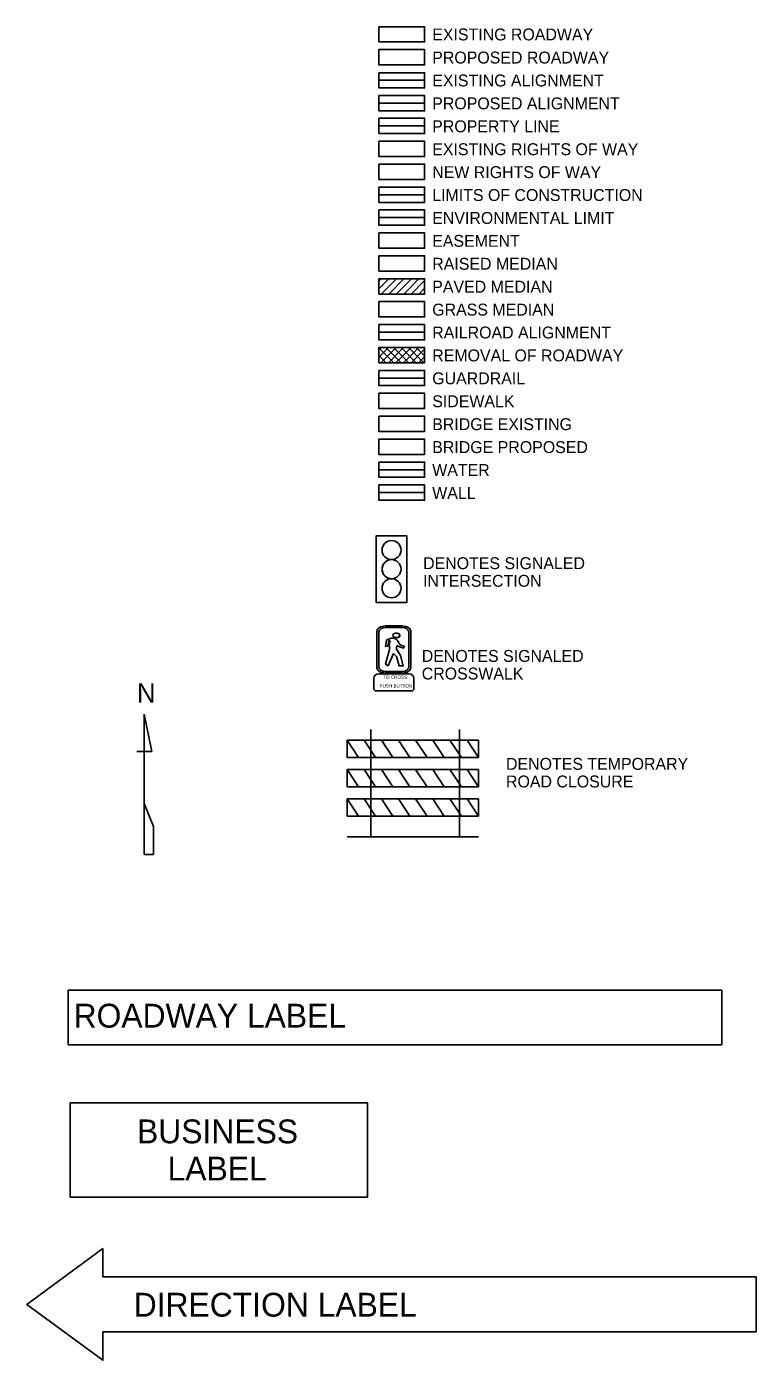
# Model space of a CAD drawing. Extents: x -1064 to 1826, y -89 to 1039.
# Drawn here: x -1064 to -602, y -89 to 755 of the extents above; entities that cross this region are included whole.
import ezdxf

# ---------------------------------------------------------------- set-up
doc = ezdxf.new("R2010")
doc.units = 0
for name, color, linetype in [('PIM_ALIGN_EX', 7, 'Continuous'), ('PIM_ALIGN_PD', 7, 'Continuous'), ('PIM_BORDER_SHEET', 7, 'Continuous'), ('PIM_BRIDGE_EX', 7, 'Continuous'), ('PIM_BRIDGE_PD', 7, 'Continuous'), ('PIM_CELLS', 7, 'Continuous'), ('PIM_CONST_LIM', 7, 'Continuous'), ('PIM_EASEMENT', 7, 'Continuous'), ('PIM_GUARDRAIL', 7, 'Continuous'), ('PIM_MED_CONC', 7, 'Continuous'), ('PIM_MED_GRASS', 7, 'Continuous'), ('PIM_PAVE_ASPH_EX', 7, 'Continuous'), ('PIM_PAVE_ASPH_PD', 7, 'Continuous'), ('PIM_PAVE_MARK', 7, 'Continuous'), ('PIM_PAVE_REMOVAL', 7, 'Continuous'), ('PIM_PROPERTY_LINE', 7, 'Continuous'), ('PIM_RAILROAD', 7, 'Continuous'), ('PIM_ROW_EX', 7, 'Continuous'), ('PIM_ROW_PD', 7, 'Continuous'), ('PIM_SW_CONC', 7, 'Continuous'), ('PIM_WALLS', 7, 'Continuous'), ('PIM_WATER', 7, 'Continuous'), ('PIM_WETLAND', 7, 'Continuous')]:
    doc.layers.add(name, color=color, linetype=linetype)

msp = doc.modelspace()

# ---------------------------------------------------------------- linework, layer by layer
at = {"layer": 'PIM_ALIGN_EX'}
msp.add_line((-841.13, 720.88), (-812.18, 720.88), dxfattribs=at)
at = {"layer": 'PIM_ALIGN_PD'}
msp.add_line((-841.13, 706.37), (-812.18, 706.37), dxfattribs=at)
at = {"layer": 'PIM_BORDER_SHEET'}
msp.add_line((-778.08, 242.07), (-861.27, 242.07), dxfattribs=at)
for points in [[(-846.17, 310.03), (-846.17, 242.07)], [(-790.11, 242.07), (-790.11, 310.03)]]:
    msp.add_lwpolyline(points, dxfattribs=at)
for points in [[(-778.08, 303.16), (-861.27, 303.16), (-861.27, 292.29), (-778.08, 292.29)], [(-861.27, 303.16), (-854.04, 292.29), (-843.19, 292.29), (-850.42, 303.16)], [(-839.57, 303.16), (-832.34, 292.29), (-821.49, 292.29), (-828.72, 303.16)], [(-817.87, 303.16), (-810.64, 292.29), (-799.78, 292.29), (-807.02, 303.16)], [(-796.17, 303.16), (-788.93, 292.29), (-778.08, 292.29), (-785.32, 303.16)], [(-778.08, 284.6), (-861.27, 284.6), (-861.27, 273.73), (-778.08, 273.73)], [(-861.27, 284.6), (-854.04, 273.73), (-843.19, 273.73), (-850.42, 284.6)], [(-839.57, 284.6), (-832.34, 273.73), (-821.49, 273.73), (-828.72, 284.6)], [(-817.87, 284.6), (-810.64, 273.73), (-799.78, 273.73), (-807.02, 284.6)], [(-796.17, 284.6), (-788.93, 273.73), (-778.08, 273.73), (-785.32, 284.6)], [(-778.08, 266.04), (-861.27, 266.04), (-861.27, 255.17), (-778.08, 255.17)], [(-861.27, 266.04), (-854.04, 255.17), (-843.19, 255.17), (-850.42, 266.04)], [(-839.57, 266.04), (-832.34, 255.17), (-821.49, 255.17), (-828.72, 266.04)], [(-817.87, 266.04), (-810.64, 255.17), (-799.78, 255.17), (-807.02, 266.04)], [(-796.17, 266.04), (-788.93, 255.17), (-778.08, 255.17), (-785.32, 266.04)], [(-1015.86, -18.43), (-1064.09, -53.86), (-1015.86, -89.28), (-1015.86, -71.19), (-602.2, -71.19), (-602.2, -36.52), (-1015.86, -36.52)]]:
    msp.add_lwpolyline(points, close=True, dxfattribs=at)
at = {"layer": 'PIM_BRIDGE_EX'}
msp.add_lwpolyline([(-841.13, 508.29), (-812.18, 508.29), (-812.18, 498.62), (-841.13, 498.62)], close=True, dxfattribs=at)
at = {"layer": 'PIM_BRIDGE_PD'}
msp.add_lwpolyline([(-841.13, 493.79), (-812.18, 493.79), (-812.18, 484.12), (-841.13, 484.12)], close=True, dxfattribs=at)
at = {"layer": 'PIM_CELLS'}
for p, q in [((-842.51, 371.74), (-842.51, 349.52)), ((-841.1, 349.52), (-841.1, 371.74)), ((-841.1, 371.74), (-841.1, 349.52)), ((-831.66, 375.52), (-836.85, 375.52)), ((-836.85, 374.57), (-831.66, 374.57)), ((-831.66, 374.57), (-836.85, 374.57)), ((-826.46, 375.52), (-831.66, 375.52)), ((-831.66, 374.57), (-826.46, 374.57)), ((-826.46, 374.57), (-831.66, 374.57)), ((-822.22, 371.74), (-822.22, 349.52)), ((-822.22, 349.52), (-822.22, 371.74)), ((-820.8, 349.52), (-820.8, 371.74)), ((-835.52, 362.66), (-834.87, 366.1)), ((-834.87, 366.1), (-835.52, 362.66)), ((-833.27, 367.74), (-833.28, 367.74)), ((-833.28, 367.74), (-833.28, 367.74)), ((-829.67, 363.24), (-828.17, 362.26)), ((-828.17, 362.26), (-829.67, 363.24)), ((-829.55, 366.61), (-827.66, 363.56)), ((-825, 362.57), (-827.66, 363.56)), ((-827.66, 363.56), (-825, 362.57)), ((-834.18, 361.49), (-837.02, 351.26)), ((-837.02, 351.26), (-834.18, 361.49)), ((-836.84, 362.62), (-835.52, 362.66)), ((-835.52, 362.66), (-836.84, 362.62)), ((-835.34, 350.23), (-831.92, 358.06)), ((-831.92, 358.06), (-835.34, 350.23)), ((-837.02, 351.26), (-835.34, 350.23)), ((-835.34, 350.23), (-837.02, 351.26)), ((-831.66, 346.68), (-836.85, 346.68)), ((-836.85, 346.68), (-831.66, 346.68)), ((-826.46, 346.68), (-831.66, 346.68)), ((-831.66, 346.68), (-826.46, 346.68)), ((-844.34, 342.34), (-844.34, 335.78)), ((-844.34, 342.34), (-844.34, 335.78)), ((-831.66, 345.22), (-841.1, 345.22)), ((-831.66, 345.22), (-841.1, 345.22)), ((-836.85, 345.74), (-831.66, 345.74)), ((-831.66, 345.74), (-826.46, 345.74)), ((-822.21, 345.22), (-831.66, 345.22)), ((-822.21, 345.22), (-831.66, 345.22)), ((-818.97, 335.78), (-818.97, 342.34)), ((-818.97, 335.78), (-818.97, 342.34)), ((-842.87, 334.47), (-831.66, 334.47)), ((-842.87, 334.47), (-831.66, 334.47)), ((-831.66, 334.47), (-820.44, 334.47)), ((-831.66, 334.47), (-820.44, 334.47)), ((-984.93, 295.99), (-989.65, 319.67)), ((-989.65, 319.67), (-989.65, 319.67)), ((-989.65, 319.67), (-989.65, 295.99)), ((-994.38, 295.99), (-989.65, 295.99)), ((-989.65, 263.12), (-989.65, 295.99)), ((-989.65, 295.99), (-984.93, 295.99)), ((-984.93, 295.99), (-984.93, 296.27)), ((-983.75, 248.62), (-989.65, 263.12)), ((-989.65, 263.12), (-989.65, 230.85)), ((-983.75, 230.85), (-983.75, 248.78)), ((-983.75, 248.78), (-983.75, 248.62)), ((-989.65, 230.85), (-983.75, 230.85))]:
    msp.add_line(p, q, dxfattribs=at)
for points in [[(-823.47, 432.62), (-842.76, 432.62), (-842.76, 390.33), (-823.47, 390.33), (-823.47, 432.62)], [(-833.28, 367.74), (-836.39, 366.45), (-836.84, 362.62)], [(-836.84, 362.62), (-836.39, 366.45), (-833.27, 367.74)], [(-834.87, 366.1), (-834.06, 366.1), (-834.59, 364.18)], [(-834.59, 364.18), (-834.06, 366.1), (-834.87, 366.1)], [(-827.66, 363.56), (-829.55, 366.61), (-829.55, 366.61)], [(-831.92, 358.06), (-830, 356.14), (-828.3, 350.23), (-825.67, 350.23), (-827.54, 356.74), (-830.18, 361.21)], [(-830.18, 361.21), (-827.54, 356.74), (-825.67, 350.23), (-828.3, 350.23), (-830, 356.14), (-831.92, 358.06)], [(-828.17, 362.26), (-825.61, 361.57), (-825, 362.57)], [(-825, 362.57), (-825.61, 361.57), (-828.17, 362.26)]]:
    msp.add_lwpolyline(points, dxfattribs=at)
for points in [[(-842.76, 432.62), (-823.47, 432.62), (-823.47, 390.33), (-842.76, 390.33)], [(-1037.8, 145.08), (-624.14, 145.08), (-624.14, 110.4), (-1037.8, 110.4)], [(-1036.5, 73.64), (-848.44, 73.64), (-848.44, 14.07), (-1036.5, 14.07)]]:
    msp.add_lwpolyline(points, close=True, dxfattribs=at)
for centre in [(-833.12, 423.56), (-833.12, 423.56), (-833.12, 423.56), (-833.12, 411.48), (-833.12, 411.48), (-833.12, 399.39), (-833.12, 399.39), (-833.12, 399.39)]:
    msp.add_ellipse(centre, major_axis=(0, 6.04), ratio=0.997778, dxfattribs=at)
for centre, major_axis, ratio, start_param, end_param in [((-833.12, 411.48), (0, 6.04), 0.997778, 0, 3.141593), ((-833.12, 411.48), (0, 6.04), 0.997778, 3.141593, 6.283185), ((-836.85, 371.74), (-5.66, 0), 0.668151, 4.712389, 6.283185), ((-836.85, 371.74), (-4.25, 0), 0.668151, 4.712389, 6.283185), ((-836.85, 371.74), (-4.25, 0), 0.668151, 4.712389, 6.283185), ((-826.46, 371.74), (5.66, 0), 0.668151, 0, 1.570796), ((-826.46, 371.74), (4.25, 0), 0.668151, 0, 1.570796), ((-826.46, 371.74), (4.25, 0), 0.668151, 0, 1.570796), ((-819.13, 363.86), (-15.46, 0), 0.668151, 6.252761, 6.515412), ((-819.13, 363.86), (-15.46, 0), 0.668151, 6.252761, 6.515412), ((-832.31, 365.85), (-2.99, 0), 0.668151, 3.53524, 5.041115), ((-832.31, 365.85), (-2.99, 0), 0.668151, 3.53524, 5.041115), ((-830.1, 369.58), (2.2, 0), 0.668151, 1.84251, 3.141593), ((-830.1, 369.58), (2.2, 0), 0.668151, 1.84251, 3.141593), ((-830.1, 369.58), (2.2, 0), 0.668151, 3.141593, 4.440675), ((-830.1, 369.58), (2.2, 0), 0.668151, 3.141593, 4.440675), ((-830.1, 369.58), (2.2, 0), 0.668151, 1.299083, 1.84251), ((-830.1, 369.58), (2.2, 0), 0.668151, 1.299083, 1.84251), ((-830.1, 369.58), (2.2, 0), 0.668151, 4.440675, 7.582268), ((-830.1, 369.58), (2.2, 0), 0.668151, 4.440675, 6.283185), ((-790.87, 357.79), (-39.65, 0), 0.668151, 6.075978, 6.153718), ((-790.87, 357.79), (-39.65, 0), 0.668151, 6.075978, 6.153718), ((-830.1, 369.58), (2.2, 0), 0.668151, 0, 1.299083), ((-836.85, 349.52), (-5.66, 0), 0.668151, 0, 1.570796), ((-836.85, 349.52), (-4.25, 0), 0.668151, 0, 1.570796), ((-836.85, 349.52), (-4.25, 0), 0.668151, 0, 1.570796), ((-826.46, 349.52), (5.66, 0), 0.668151, 4.712389, 6.283185), ((-826.46, 349.52), (4.25, 0), 0.668151, 4.712389, 6.283185), ((-826.46, 349.52), (4.25, 0), 0.668151, 4.712389, 6.283185), ((-841.1, 342.34), (-3.24, 0), 0.890869, 4.712389, 6.283185), ((-841.1, 342.34), (-3.24, 0), 0.890869, 4.712389, 6.283185), ((-822.21, 342.34), (3.24, 0), 0.890869, 0, 1.570796), ((-822.21, 342.34), (3.24, 0), 0.890869, 0, 1.570796), ((-842.87, 335.78), (1.47, 0), 0.890869, 3.141593, 4.712389), ((-842.87, 335.78), (1.47, 0), 0.890869, 3.141593, 4.712389), ((-820.44, 335.78), (1.47, 0), 0.890869, 4.712389, 6.283185), ((-820.44, 335.78), (1.47, 0), 0.890869, 4.712389, 6.283185)]:
    msp.add_ellipse(centre, major_axis=major_axis, ratio=ratio, start_param=start_param, end_param=end_param, dxfattribs=at)
at = {"layer": 'PIM_CONST_LIM'}
msp.add_line((-841.13, 648.49), (-812.18, 648.49), dxfattribs=at)
at = {"layer": 'PIM_EASEMENT'}
msp.add_lwpolyline([(-841.13, 624.32), (-812.18, 624.32), (-812.18, 614.65), (-841.13, 614.65)], close=True, dxfattribs=at)
at = {"layer": 'PIM_GUARDRAIL'}
msp.add_line((-841.13, 532.46), (-812.18, 532.46), dxfattribs=at)
at = {"layer": 'PIM_MED_CONC'}
msp.add_lwpolyline([(-812.18, 600.14), (-812.18, 609.81), (-841.13, 609.81), (-841.13, 600.14), (-812.18, 600.14)], dxfattribs=at)
msp.add_lwpolyline([(-841.13, 609.81), (-812.18, 609.81), (-812.18, 600.14), (-841.13, 600.14)], close=True, dxfattribs=at)
at = {"layer": 'PIM_MED_GRASS'}
for points in [[(-841.13, 696.83), (-812.18, 696.83), (-812.18, 687.16), (-841.13, 687.16)], [(-841.13, 653.32), (-812.18, 653.32), (-812.18, 643.65), (-841.13, 643.65)], [(-841.13, 638.82), (-812.18, 638.82), (-812.18, 629.15), (-841.13, 629.15)], [(-841.13, 580.81), (-812.18, 580.81), (-812.18, 571.14), (-841.13, 571.14)], [(-841.13, 479.29), (-812.18, 479.29), (-812.18, 469.62), (-841.13, 469.62)], [(-841.13, 464.78), (-812.18, 464.78), (-812.18, 455.11), (-841.13, 455.11)]]:
    msp.add_lwpolyline(points, close=True, dxfattribs=at)
at = {"layer": 'PIM_PAVE_ASPH_EX'}
for points in [[(-841.13, 754.84), (-812.18, 754.84), (-812.18, 745.17), (-841.13, 745.17)], [(-841.13, 725.71), (-812.18, 725.71), (-812.18, 716.04), (-841.13, 716.04)], [(-841.13, 711.21), (-812.18, 711.21), (-812.18, 701.54), (-841.13, 701.54)], [(-841.13, 566.3), (-812.18, 566.3), (-812.18, 556.63), (-841.13, 556.63)], [(-841.13, 551.8), (-812.18, 551.8), (-812.18, 542.13), (-841.13, 542.13)]]:
    msp.add_lwpolyline(points, close=True, dxfattribs=at)
at = {"layer": 'PIM_PAVE_ASPH_PD'}
for points in [[(-841.13, 740.34), (-812.18, 740.34), (-812.18, 730.67), (-841.13, 730.67)], [(-841.13, 537.3), (-812.18, 537.3), (-812.18, 527.63), (-841.13, 527.63)]]:
    msp.add_lwpolyline(points, close=True, dxfattribs=at)
at = {"layer": 'PIM_PAVE_MARK'}
for p, q in [((-841.13, 589.01), (-834.84, 595.31)), ((-841.13, 593.79), (-839.61, 595.31)), ((-839.71, 585.64), (-830.06, 595.31)), ((-834.93, 585.64), (-825.29, 595.31)), ((-830.16, 585.64), (-820.51, 595.31)), ((-825.38, 585.64), (-815.74, 595.31)), ((-820.61, 585.64), (-812.18, 594.08)), ((-813.06, 595.31), (-812.18, 594.43)), ((-815.83, 585.64), (-812.18, 589.3))]:
    msp.add_line(p, q, dxfattribs=at)
msp.add_lwpolyline([(-841.13, 595.31), (-812.18, 595.31), (-812.18, 585.64), (-841.13, 585.64)], close=True, dxfattribs=at)
msp.add_lwpolyline([(-841.13, 585.64), (-812.18, 585.64), (-812.18, 595.31), (-841.13, 595.31), (-841.13, 585.64)], dxfattribs=at)
at = {"layer": 'PIM_PAVE_REMOVAL'}
for p, q in [((-841.13, 545.66), (-835, 551.8)), ((-841.13, 550.44), (-839.77, 551.8)), ((-841.13, 551.5), (-831.77, 542.13)), ((-839.87, 542.13), (-830.22, 551.8)), ((-836.65, 551.8), (-827, 542.13)), ((-835.09, 542.13), (-825.45, 551.8)), ((-831.87, 551.8), (-822.22, 542.13)), ((-830.32, 542.13), (-820.67, 551.8)), ((-827.1, 551.8), (-817.45, 542.13)), ((-825.54, 542.13), (-815.9, 551.8)), ((-822.32, 551.8), (-812.67, 542.13)), ((-820.77, 542.13), (-812.18, 550.74)), ((-817.55, 551.8), (-812.18, 546.43)), ((-812.77, 551.8), (-812.18, 551.21)), ((-841.13, 546.72), (-836.55, 542.13)), ((-815.99, 542.13), (-812.18, 545.95))]:
    msp.add_line(p, q, dxfattribs=at)
msp.add_lwpolyline([(-841.13, 542.13), (-812.18, 542.13), (-812.18, 551.8), (-841.13, 551.8), (-841.13, 542.13)], dxfattribs=at)
at = {"layer": 'PIM_PROPERTY_LINE'}
msp.add_line((-841.13, 692), (-812.18, 692), dxfattribs=at)
at = {"layer": 'PIM_RAILROAD'}
msp.add_line((-841.13, 561.47), (-812.18, 561.47), dxfattribs=at)
at = {"layer": 'PIM_ROW_EX'}
msp.add_lwpolyline([(-841.13, 682.33), (-812.18, 682.33), (-812.18, 672.66), (-841.13, 672.66)], close=True, dxfattribs=at)
msp.add_lwpolyline([(-841.13, 682.33), (-812.18, 682.33), (-812.18, 672.66), (-841.13, 672.66)], close=True, dxfattribs=at)
at = {"layer": 'PIM_ROW_PD'}
for p, q in [((-841.13, 667.82), (-812.18, 667.82)), ((-841.13, 658.16), (-841.13, 667.82)), ((-812.18, 667.82), (-812.18, 658.16)), ((-812.18, 658.16), (-841.13, 658.16))]:
    msp.add_line(p, q, dxfattribs=at)
msp.add_lwpolyline([(-841.13, 667.82), (-812.18, 667.82), (-812.18, 658.16), (-841.13, 658.16)], close=True, dxfattribs=at)
at = {"layer": 'PIM_SW_CONC'}
msp.add_lwpolyline([(-841.13, 522.79), (-812.18, 522.79), (-812.18, 513.13), (-841.13, 513.13)], close=True, dxfattribs=at)
at = {"layer": 'PIM_WALLS'}
msp.add_line((-841.13, 459.95), (-812.18, 459.95), dxfattribs=at)
at = {"layer": 'PIM_WATER'}
msp.add_line((-841.13, 474.45), (-812.18, 474.45), dxfattribs=at)
at = {"layer": 'PIM_WETLAND'}
msp.add_line((-841.13, 633.98), (-812.18, 633.98), dxfattribs=at)

# ---------------------------------------------------------------- texts
at = {"layer": 'PIM_BORDER_SHEET'}
for s, height, p in [('EXISTING ROADWAY', 7.5353, (-807.36, 746.15)), ('PROPOSED ROADWAY', 7.5353, (-807.36, 731.52)), ('EXISTING ALIGNMENT', 7.5353, (-807.36, 717.02)), ('PROPOSED ALIGNMENT', 7.5353, (-807.36, 702.52)), ('PROPERTY LINE', 7.5353, (-807.36, 688.02)), ('EXISTING RIGHTS OF WAY', 7.5353, (-807.36, 673.51)), ('NEW RIGHTS OF WAY', 7.5353, (-807.36, 659.01)), ('LIMITS OF CONSTRUCTION', 7.5353, (-807.36, 644.51)), ('ENVIRONMENTAL LIMIT', 7.5353, (-807.36, 630)), ('EASEMENT', 7.535, (-807.36, 615.5)), ('RAISED MEDIAN', 7.5353, (-807.36, 601)), ('PAVED MEDIAN', 7.5353, (-807.36, 586.5)), ('GRASS MEDIAN', 7.5353, (-807.36, 571.99)), ('RAILROAD ALIGNMENT', 7.5353, (-807.36, 557.49)), ('REMOVAL OF ROADWAY', 7.5353, (-807.36, 542.99)), ('GUARDRAIL', 7.535, (-807.36, 528.48)), ('SIDEWALK', 7.535, (-807.36, 513.98)), ('BRIDGE EXISTING', 7.5353, (-807.36, 499.48)), ('BRIDGE PROPOSED', 7.5353, (-807.36, 484.97)), ('WATER', 7.535, (-807.36, 470.47)), ('WALL', 7.535, (-807.36, 455.97)), ('DENOTES SIGNALED', 7.5353, (-813.14, 411.49)), ('INTERSECTION', 7.5353, (-813.14, 400.33)), ('DENOTES SIGNALED', 7.5353, (-814, 352.8)), ('CROSSWALK', 7.535, (-814, 341.64)), ('DENOTES TEMPORARY', 7.5353, (-760.65, 284.49)), ('ROAD CLOSURE', 7.5353, (-760.65, 273.33))]:
    msp.add_text(s, height=height, dxfattribs=at).set_placement(p)
at = {"layer": 'PIM_CELLS'}
for s, height, p in [('N', 12.08, (-994.27, 327.05)), ('PUSH BUTTON', 2.0981, (-840.74, 336.57)), ('TO CROSS', 2.098, (-838.43, 342.07)), ('ROADWAY LABEL', 15.0707, (-1034.39, 121.32)), ('BUSINESS', 15.071, (-994.23, 48.09)), ('LABEL', 15.071, (-974.9, 24.56)), ('DIRECTION LABEL', 15.0707, (-996.33, -61.62))]:
    msp.add_text(s, height=height, dxfattribs=at).set_placement(p)

doc.saveas('drawing.dxf')
